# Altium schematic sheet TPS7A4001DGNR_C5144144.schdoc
size 127 x 101 mm
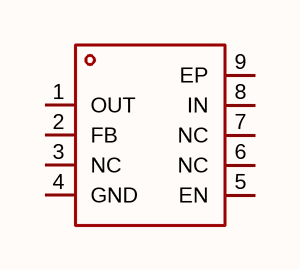
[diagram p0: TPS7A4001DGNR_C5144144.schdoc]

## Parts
U?  tps7a4001dgnr_c5144144  [MSOP-8_L3.0-W3.0-P0.65-LS4.9-BL-EP2.4]  (value not drawn)

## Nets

Not connected (* = marked no-connect by the designer): U? 1(OUT) 2(FB) 3(NC) 4(GND) 5(EN) 6(NC) 7(NC) 8(IN) 9(EP)

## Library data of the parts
U? = tps7a4001dgnr_c5144144: 输出极性:正极;工作电压:100V;输出电压:1.2V~90V;输出电流:50mA;电源纹波抑制比(PSRR):-;输出类型:可调;; Manufacturer: JSMSEMI(杰盛微); AddInBom: yes; ModelId: 22455536c6c3483da1361c3a9374ed9c; ModelTransform: 118.11,192.913,0,0,0,0,0,0,0; Output Configuration: 正极; Voltage - Supply: 100V; Output Current: 50mA; Voltage Dropout: 2.8V@(50mA); standby current: 23uA; Output Type: 可调; Number of Outputs: 1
